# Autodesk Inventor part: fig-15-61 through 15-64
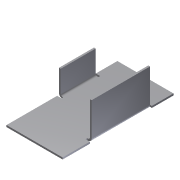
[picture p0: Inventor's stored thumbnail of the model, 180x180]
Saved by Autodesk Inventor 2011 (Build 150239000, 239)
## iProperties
Shininess: 77.0
Angle Display Precision: 2
Document Length Units: 11269
Document Angle Units: 11279
Document Time Units: 11290
Document Mass Units: 11283
Document Length Units Precision: 3
Document Angle Units Precision: 2
Compacted: True
Created: 2002-04
Part Number: fig-15-61 through 15-64
Document SubType Name: Sheet Metal
Density: 1 g/cm^3
Sheet Metal Rule: Default
Density: 0.0
Volumn: 0.0
Area: 0.0
PropertySet Name: Model Information
Control State: 0
Master: False
Checked Out: False
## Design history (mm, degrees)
node "Face1"
  sketch "Sketch1"
    geometry: L1 (-33.176, 5.765)-(14.235, 5.765); L2 (14.235, 5.765)-(14.235, -18.235); L3 (14.235, -18.235)-(-33.176, -18.235); L4 (-33.176, -18.235)-(-33.176, 5.765)
    constraints: 8 end point, 2 parallel, 1 horizontal, 1 perpendicular
node "Flange1"
node "Flange2"
body "Solid1"
face "Plate1" dims "Thickness" = 0.75
sketch "Sketch2"
  geometry: L1 (37.412, 0)-(22.412, 0); L2 (22.412, 0)-(22.412, 10); L3 (22.412, 10)-(37.412, 10); L4 (37.412, 10)-(37.412, 0)
  constraints: 8 end point
face "Plate2" dims "d1" = 10, "d2" = 15, "d4" = 10, "d5" = 90 deg, "d6" = 0.75 (= BendRadius), "Thickness" = 0.75, "MinimumRemnant" = 1.5 (= 2 x Thickness), "BendReliefWidth" = 0.75 (= Thickness)
bend "Bend1" dims "d3" = 0.75 (= BendRadius), "d4" = 10, "d5" = 90 deg, "d6" = 0.75 (= BendRadius), "d15" = 0.75 (= BendReliefWidth), "d16" = 0.375 (= BendReliefDepth), "d17" = 1.5 (= MinimumRemnant), "SeamGap" = 0.01, "Thickness" = 0.75, "MinimumRemnant" = 1.5 (= 2 x Thickness), "BendReliefWidth" = 0.75 (= Thickness)
sketch "Sketch3"
  geometry: L1 (10, 0)-(35, 0); L2 (35, 0)-(35, 15); L3 (35, 15)-(10, 15); L4 (10, 15)-(10, 0)
  constraints: 8 end point
face "Plate3" dims "d7" = 10, "d8" = 25, "d10" = 15, "d11" = 90 deg, "d12" = 0.75 (= BendRadius), "Thickness" = 0.75, "MinimumRemnant" = 1.5 (= 2 x Thickness), "BendReliefWidth" = 0.75 (= Thickness)
bend "Bend2" dims "d9" = 0.75 (= BendRadius), "d10" = 15, "d11" = 90 deg, "d12" = 0.75 (= BendRadius), "d18" = 0.75 (= BendReliefWidth), "d19" = 0.375 (= BendReliefDepth), "d20" = 1.5 (= MinimumRemnant), "SeamGap" = 0.01, "Thickness" = 0.75, "MinimumRemnant" = 1.5 (= 2 x Thickness), "BendReliefWidth" = 0.75 (= Thickness)
other parameters: "BendRadius" = 0.75 (= Thickness), "BendReliefDepth" = 0.375 (= 0.5 x Thickness), "CornerReliefSize" = 3 (= 4 x Thickness), "TransitionRadius" = 0.75 (= BendRadius), "d0" = 0.75 (= BendRadius), "d13" = 0.75 (= BendRadius), "JacobiRadiusSize" = 0.75 (= Thickness), "GapSize" = 0.75 (= Thickness)
